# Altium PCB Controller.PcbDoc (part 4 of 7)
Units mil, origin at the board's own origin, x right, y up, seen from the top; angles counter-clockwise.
Board outline 9000 x 8000 mil, 6 copper layers (Top Layer, Layer 1, Layer 2, Layer 3, Layer 4, Bottom Layer), stack 61.699 mil thick; 761 components, 454 nets, 2369 pads, 1133 vias.
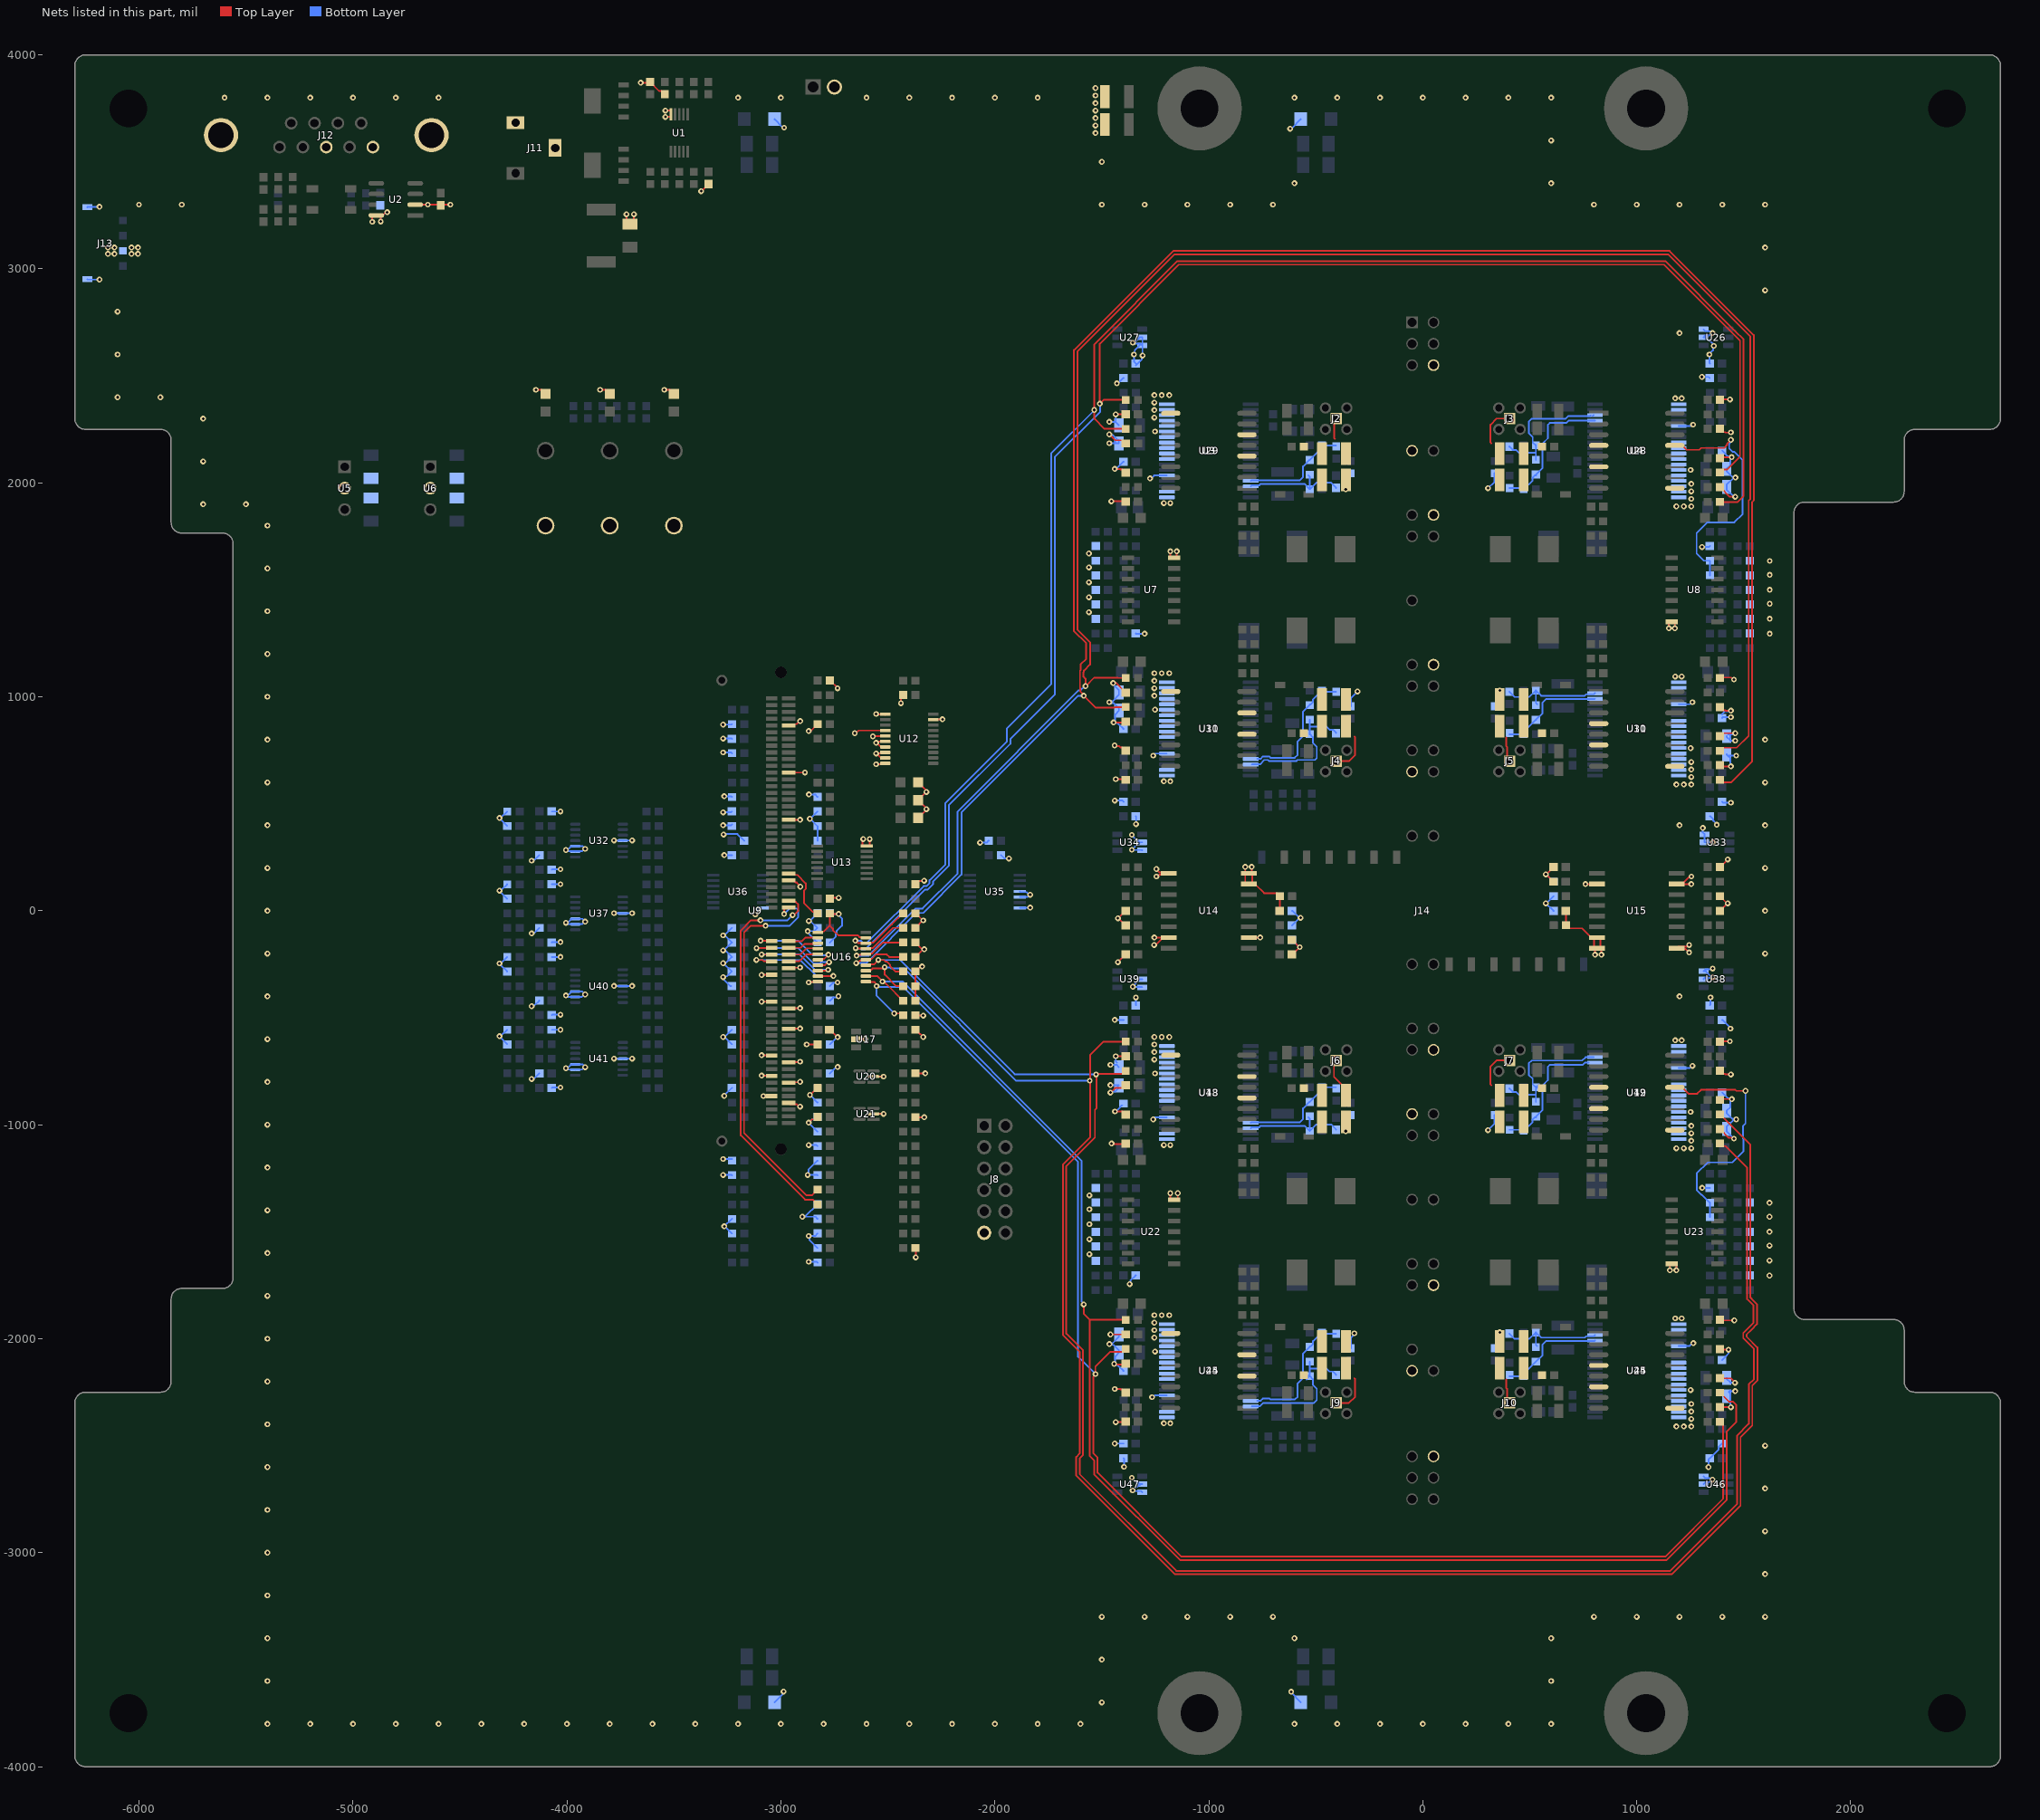
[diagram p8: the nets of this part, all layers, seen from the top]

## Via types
v1: diameter 27, hole 13, Top Layer to Bottom Layer, tented both sides, 1133 vias

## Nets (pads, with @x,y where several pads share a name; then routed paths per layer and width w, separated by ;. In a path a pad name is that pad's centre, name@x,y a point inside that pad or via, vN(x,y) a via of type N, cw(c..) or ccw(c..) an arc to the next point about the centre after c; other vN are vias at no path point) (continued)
F\L\T\_\4\P\: R193.1 R195.2 U4.13 | length 1165.1
  Top Layer w8: U4.13@1177.78,2175 1211.65,2175 1232.15,2154.5 1291.65,2154.5 1300.01,2162.86 1407.86,2162.86 1422.12,2177.12 1422.12,2182.77 1439.89,2200.55 v1(1439.89,2201.06)
  Bottom Layer w8: R195.2@1341.38,1568 R193.1@1341.38,1636 1314,1636 1279.7,1670.3 1279.7,1764.7 1330,1815 1456.06,1815 1495,1853.94 1495,2105 1454.69,2145.31 1446.94,2145.31 1432,2160.25 1432,2181.38 1436.25,2185.63 1436.25,2197.43 v1(1439.89,2201.06)
F\L\T\_\4\S\: R336.1 R339.2 U19.13 | length 1134
  Top Layer w8: U19.13@1177.78,-825 1211.65,-825 1241.65,-855 1282.15,-855 1300.01,-837.14 1460.33,-837.14 1464.94,-841.75 v1(1508.25,-841.75)
  Bottom Layer w8: R339.2@1341.38,-1432 R336.1@1341.38,-1364 1340.47,-1364 1304.28,-1327.8 1302.24,-1327.8 1280,-1305.56 1280,-1227.63 1331.63,-1176 1446.63,-1176 1499,-1123.63 1499,-1066.89 1496,-1063.89 1496,-1007.14 1508.25,-994.89 v1(1508.25,-841.75)
FBVDD_1P: C130.1 R212.1 R215.2 U30.34 | length 503.5
  Bottom Layer w8: C130.1@405,1023.58 405,1022.63 428.58,999.04 497.76,999.04 527.72,1029 R212.1@528.62,1029 ; R215.2@535,965 528.62,971.38 R212.1@528.62,1029 ; U30.34@804.13,1016.34 799.4,1011.61 763.89,1011.61 757.28,1005 553.53,1005 529.53,1029 R212.1@528.62,1029
FBVDD_1S: C249.1 R362.1 R365.2 U44.34 | length 503.5
  Bottom Layer w8: C249.1@405,-1976.42 405,-1977.37 428.58,-2000.96 497.76,-2000.96 527.72,-1971 R362.1@528.62,-1971 ; R365.2@535,-2035 528.62,-2028.62 R362.1@528.62,-1971 ; U44.34@804.13,-1983.66 799.4,-1988.39 763.89,-1988.39 757.28,-1995 553.53,-1995 529.53,-1971 R362.1@528.62,-1971
FBVDD_2P: C139.1 R219.2 R224.1 U31.34 | length 647.2
  Bottom Layer w8: U31.34@-798.66,683.66 -797.73,684.6 -760.4,684.6 -740,705 -724.28,705 -718.28,699 -591.72,699 -585.72,705 -503.88,705 -495.36,713.52 -495.36,766.98 -513.76,785.39 -513.76,811.04 -527.72,825 R224.1@-528.62,825 -528.62,860 R219.2@-528.62,893 ; -525,860 -450,860 -436.24,846.24 -419.86,846.24 -405,831.37 C139.1@-405,830.42
FBVDD_2S: C257.1 R368.2 R371.1 U45.34 | length 662.6
  Bottom Layer w8: U45.34@-798.66,-2316.34 -797.73,-2315.4 -760.4,-2315.4 -745,-2300 -508.88,-2300 -495.36,-2286.48 -495.36,-2233.02 -513.76,-2214.61 -513.76,-2188.96 -527.72,-2175 R371.1@-528.62,-2175 R371.1@-529.53,-2175 ; R371.1@-543.48,-2189.86 -543.48,-2188.96 R371.1@-532.26,-2177.74 ; R371.1@-535,-2175 -528.62,-2168.62 R368.2@-528.62,-2107 ; -525,-2140 -450,-2140 -436.24,-2153.76 -419.86,-2153.76 -405,-2168.63 C257.1@-405,-2169.58
FBVDD_3P: C111.1 R181.2 R184.1 U29.34 | length 503.5
  Bottom Layer w8: U29.34@-804.13,1983.66 -799.4,1988.39 -763.89,1988.39 -757.28,1995 -553.53,1995 -529.53,1971 R184.1@-528.62,1971 ; R181.2@-535,2035 -528.62,2028.62 R184.1@-528.62,1971 ; C111.1@-405,1976.42 -405,1977.37 -428.58,2000.96 -497.76,2000.96 -527.72,1971 R184.1@-528.62,1971
FBVDD_3S: C226.1 R318.2 R322.1 U43.34 | length 503.5
  Bottom Layer w8: U43.34@-804.13,-1016.34 -799.4,-1011.61 -763.89,-1011.61 -757.28,-1005 -553.53,-1005 -529.53,-1029 R322.1@-528.62,-1029 ; R318.2@-535,-965 -528.62,-971.38 R322.1@-528.62,-1029 ; C226.1@-405,-1023.58 -405,-1022.63 -428.58,-999.04 -497.76,-999.04 -527.72,-1029 R322.1@-528.62,-1029
FBVDD_4P: C100.1 R174.1 R177.2 U28.34 | length 634.7
  Bottom Layer w8: C100.1@405,2169.58 405,2168.63 419.86,2153.76 436.24,2153.76 450,2140 525,2140 ; R177.2@528.62,2107 R174.1@528.62,2175 527.72,2175 513.76,2188.96 513.76,2214.61 495.36,2233.02 495.36,2286.48 508.88,2300 667.37,2300 678.98,2311.61 781.61,2311.61 U28.34@785,2315 ; U28.34@793.93,2311.61 U28.34@798.66,2316.34
FBVDD_4S: C216.1 R306.1 R312.2 U42.34 | length 662.6
  Bottom Layer w8: C216.1@405,-830.42 405,-831.37 419.86,-846.24 436.24,-846.24 450,-860 525,-860 ; R312.2@528.62,-893 528.62,-831.38 R306.1@535,-825 ; R306.1@529.53,-825 R306.1@528.62,-825 527.72,-825 513.76,-811.04 513.76,-785.39 495.36,-766.98 495.36,-713.52 508.88,-700 745,-700 760.4,-684.6 797.73,-684.6 U42.34@798.66,-683.66 ; R306.1@532.26,-822.26 543.48,-811.04 R306.1@543.48,-810.14
FBVEE_1P: C138.1 R220.2 R223.1 U30.33 | length 504.5
  Bottom Layer w8: R220.2@405,825 R223.1@471.38,825 472.28,825 486.24,838.96 486.24,851.61 527.63,893 C138.1@528.58,893 529.53,893 560,923.47 560,973.47 575.53,989 802.39,989 U30.33@804.13,990.75
FBVEE_1S: C256.1 R369.2 R370.1 U44.33 | length 504.5
  Bottom Layer w8: R369.2@405,-2175 R370.1@471.38,-2175 472.28,-2175 486.24,-2161.04 486.24,-2148.39 527.63,-2107 C256.1@528.58,-2107 529.53,-2107 560,-2076.53 560,-2026.53 575.53,-2011 802.39,-2011 U44.33@804.13,-2009.25
FBVEE_2P: C133.1 R213.1 R214.2 U31.33 | length 619.1
  Bottom Layer w8: U31.33@-775,710 -757.63,710 -746.63,721 -717.66,721 -711.66,715 -598.34,715 -584.64,728.7 -584.64,791.36 -559.48,816.52 -559.48,931.04 C133.1@-529.05,961.48 ; C133.1@-529.05,965 -523.63,965 -512.76,975.86 -512.76,988.52 -472.28,1029 -466.91,1023.62 R214.2@-405,1023.62
FBVEE_2S: C252.1 R363.1 R364.2 U45.33 | length 617
  Bottom Layer w8: U45.33@-775,-2290 -757.63,-2290 -747.63,-2280 -716.66,-2280 -713.12,-2283.54 -596.88,-2283.54 -584.64,-2271.3 -584.64,-2208.39 -559.48,-2183.23 -559.48,-2068.96 C252.1@-529.05,-2038.52 ; C252.1@-529.05,-2035 -523.63,-2035 -512.76,-2024.14 -512.76,-2011.48 -472.28,-1971 -466.91,-1976.38 R364.2@-405,-1976.38
FBVEE_3P: C105.1 R175.1 R176.2 U29.33 | length 504.5
  Bottom Layer w8: U29.33@-804.13,2009.25 -802.39,2011 -575.53,2011 -560,2026.53 -560,2076.53 -529.53,2107 C105.1@-528.58,2107 -527.63,2107 -486.24,2148.39 -486.24,2161.04 -472.28,2175 R175.1@-471.38,2175 R176.2@-405,2175
FBVEE_3S: C219.1 R307.1 R311.2 U43.33 | length 504.5
  Bottom Layer w8: U43.33@-804.13,-990.75 -802.39,-989 -575.53,-989 -560,-973.47 -560,-923.47 -529.53,-893 C219.1@-528.58,-893 -527.63,-893 -486.24,-851.61 -486.24,-838.96 -472.28,-825 R307.1@-471.38,-825 R311.2@-405,-825
FBVEE_4P: C109.1 R182.2 R183.1 U28.33 | length 643.6
  Bottom Layer w8: R182.2@405,1976.38 466.91,1976.38 472.28,1971 512.76,2011.48 512.76,2024.14 523.63,2035 C109.1@529.05,2035 ; C109.1@529.05,2038.52 559.48,2068.96 559.48,2183.23 584.64,2208.39 584.64,2271.3 593.34,2280 670,2280 680.75,2290.75 U28.33@804.13,2290.75
FBVEE_4S: C223.1 R320.2 R321.1 U42.33 | length 614.1
  Bottom Layer w8: R320.2@405,-1023.62 466.91,-1023.62 472.28,-1029 512.76,-988.52 512.76,-975.86 523.63,-965 C223.1@529.05,-965 ; C223.1@529.05,-961.48 559.48,-931.04 559.48,-816.77 584.64,-791.61 584.64,-728.7 593.34,-720 747.63,-720 757.63,-710 U42.33@775,-710
G1P_PWM: U9.49 U16.5 | length 150.1
  Top Layer w8: U9.49@-2963.58,-236.22 -2913.54,-236.22 -2880.52,-203.2 U16.5@-2827.2,-203.2
G1P_PWM_BUF: R46.1 R57.1 R83.2 U16.15 | length 9592.6
  Top Layer w8: v1(-2647.6,-244.65) -2642.54,-244.65 -2630.55,-232.67 -2606.67,-232.67 -2598.92,-224.92 -2575.98,-224.92 -2555.56,-204.5 -2505.27,-204.5 -2493.77,-216 R83.2@-2428.62,-216 ; R46.1@-1388.62,952 -1438.27,952 -1440.77,949.5 -1529.5,949.5 v1(-1585,1005) -1585,1009.06 -1601,1025.06 -1601,1038.44 -1602,1039.44 -1602,1121.63 -1599.47,1124.16 -1599.47,1150.53 -1573.5,1176.5 -1573.5,1250.34 -1630,1306.84 -1630,2620.51 -1166.51,3084 1153.12,3084 1547,2690.12 1547,1918.06 1539,1910.06 1539,697.94 1440.56,599.5 1401.12,599.5 R57.1@1388.62,612
  Bottom Layer w8: v1(-2647.6,-244.65) -2647.51,-244.56 -2601.74,-244.56 -2367.18,-10 -2335,-10 -2156,169 -2156,459 -1610.5,1004.5 -1585.5,1004.5 v1(-1585,1005)
G1S_PWM: U9.50 U16.9 | length 537.8
  Top Layer w8: v1(-3114.5,-230) -3085.75,-230 -3080.9,-234.85 -3043.69,-234.85 U9.50@-3042.32,-236.22 ; U16.9@-2827.2,-305.57 -2826.64,-305 v1(-2755,-305)
  Bottom Layer w8: v1(-3114.5,-230) -2908.94,-230 -2833.94,-305 v1(-2755,-305)
G1S_PWM_BUF: R92.2 R148.1 R155.1 U16.11 | length 6836.6
  Top Layer w8: U16.11@-2596.35,-332.34 -2595.61,-333.08 -2562.25,-333.08 -2548.06,-347.27 v1@-2548.06,-348 ; v1(-2552.83,-351.72) -2551.78,-351.72 v1@-2548.06,-348 ; v1@-2548.06,-359.13 v1@-2548.06,-348 ; v1(-2470,-480) -2436.62,-480 R92.2@-2428.62,-488 R92.2@-2429.53,-488 ; R148.1@-1388.62,-2048 -1402.58,-2061.96 -1461.96,-2061.96 -1530,-2130 -1530,-2169.19 -1540,-2179.19 -1540,-2535 -1520,-2555 -1520,-2626.35 -1127.72,-3018.63 1132.72,-3018.63 1403.48,-2747.87 1403.48,-2401.96 1389.53,-2388 R155.1@1388.62,-2388
  Bottom Layer w8: v1(-2470,-480) -2552.83,-397.17 v1(-2552.83,-351.72) -2549.2,-355.36 -2536.2,-355.36 -2535.56,-356 -2429,-356 -1611,-1174 -1611,-2084 v1(-1530,-2165)
G2P_PWM: U9.51 U16.4 | length 150.3
  Top Layer w8: U9.51@-2963.58,-204.72 -2910.58,-204.72 -2880.86,-175 U16.4@-2825.57,-175
G2P_PWM_BUF: R40.1 R53.1 R81.2 U16.16 | length 9337.7
  Top Layer w8: v1(-2646.15,-209.68) -2642.91,-206.44 -2607.26,-206.44 U16.16@-2603.41,-202.59 ; U16.16@-2602.8,-203.2 -2598.92,-199.33 -2573.02,-199.33 -2521.69,-148 R81.2@-2428.62,-148 ; R40.1@-1389.53,1088 -1425.62,1088 -1427.21,1089.59 -1449.35,1089.59 -1449.44,1089.5 -1535.5,1089.5 -1575,1050 v1(-1576.5,1050) -1576.5,1084.38 -1586,1093.88 -1586,1115 -1583.47,1117.53 -1583.47,1122.59 -1555,1151.06 -1555,1254.47 -1614,1313.47 -1614,2613.88 -1159.88,3068 1146.49,3068 1531,2683.49 1531,1924.68 1523,1916.68 1523,818 1466.96,761.96 1402.58,761.96 R53.1@1388.62,748
  Bottom Layer w8: v1(-2646.15,-209.68) -2646.06,-209.59 -2589.4,-209.59 -2369.81,10 -2337.63,10 -2175,172.63 -2175,462.63 -1607.63,1030 -1599.69,1030 -1579.69,1050 v1(-1576.5,1050)
G2S_PWM: U9.52 U16.8 | length 438.1
  Top Layer w8: v1(-3090,-204.5) -3089.89,-204.61 -3042.44,-204.61 U9.52@-3042.32,-204.72 ; U16.8@-2827.2,-279.98 -2790.12,-279.98 -2789.69,-279.55 -2782.72,-279.55 v1(-2779.09,-275.91)
  Bottom Layer w8: v1(-3090,-204.5) -2911.81,-204.5 -2840.4,-275.91 v1(-2779.09,-275.91)
G2S_PWM_BUF: R90.2 R144.1 R153.1 U16.12 | length 6959.8
  Top Layer w8: U16.12@-2602.8,-305.57 -2602.51,-305.28 -2549.72,-305.28 v1@-2525,-330 ; v1(-2525,-330.5) v1@-2525,-330 ; R90.2@-2428.62,-420 -2429.53,-420 -2504.58,-344.95 -2504.91,-344.95 -2512.15,-337.71 -2512.65,-337.71 -2519.86,-330.5 -2519.86,-330 v1@-2525,-330 ; v1(-1585,-1840) -1585,-1883 -1556,-1912 ; R144.1@-1388.62,-1912 -1556,-1912 ; R153.1@1388.62,-2252 1389.53,-2252 1432.03,-2294.5 1450.56,-2294.5 1465.5,-2309.44 1465.5,-2388.48 1420,-2433.98 1420,-2753.98 1139.35,-3034.63 -1134.35,-3034.63 -1536,-2632.98 -1536,-2569 -1556,-2549 -1556,-1912
  Bottom Layer w8: v1(-2525,-330.5) -2524.5,-330 -2432.37,-330 -1595,-1167.37 -1595,-1825.81 -1585,-1835.81 v1(-1585,-1840)
G3P_PWM: U9.53 U16.3 | length 147.4
  Top Layer w8: U9.53@-2963.58,-173.23 -2907.63,-173.23 -2889.4,-155 U16.3@-2823.73,-155
G3P_PWM_BUF: R16.1 R23.1 R79.2 U16.17 | length 7692.7
  Top Layer w8: v1(-2650.66,-174.97) -2649.34,-176.29 -2606.5,-176.29 -2603.99,-178.81 -2598.92,-173.74 -2570.06,-173.74 -2476.32,-80 R79.2@-2428.62,-80 ; v1(-1509.5,2370) -1509.5,2650.5 -1140,3020 1126.61,3020 1483,2663.61 1483,2123.34 1421.61,2061.96 1402.58,2061.96 R23.1@1388.62,2048 ; v1@-1509.5,2370.44 -1491.94,2388 R16.1@-1388.62,2388
  Bottom Layer w8: v1(-2650.66,-174.97) -2648.1,-177.54 -2625.16,-177.54 -2622.7,-180 -2605,-180 -2325.95,99.05 -2320.7,99.05 -2320.46,99.29 -2313.15,99.29 -2289,123.44 -2289,136 -2215,210 -2215,492.63 -1927.5,780.13 -1927.5,802.5 -1720,1010 -1720,2120 -1507.53,2332.47 -1507.53,2368.03 v1(-1509.5,2370)
G3S_PWM: U9.54 U16.7 | length 500.5
  Top Layer w8: v1(-3113.92,-174.9) -3113.09,-174.06 -3043.16,-174.06 U9.54@-3042.32,-173.23 ; U16.7@-2827.2,-254.39 -2794.39,-254.39 -2780,-240 v1(-2775,-240)
  Bottom Layer w8: v1(-3113.92,-174.9) -2918.78,-174.9 -2848.68,-245 -2816.91,-245 -2811.91,-240 v1(-2775,-240)
G3S_PWM_BUF: R88.2 R94.1 R109.1 U16.13 | length 9082.6
  Top Layer w8: U16.13@-2620.47,-275 -2576.1,-275 -2570.34,-269.25 -2545.75,-269.25 -2545,-270 v1@-2515,-270 ; v1(-2515,-263.5) v1@-2515,-270 ; R88.2@-2428.62,-352 -2461.49,-352 -2515,-298.49 v1@-2515,-270 ; v1(-1556.5,-794.17) -1555,-795.67 -1555,-1059.75 -1682,-1186.75 -1682,-1982.75 -1604,-2060.75 -1604,-2536.63 -1620,-2552.63 -1620,-2639.49 -1158.49,-3101 1163.49,-3101 1484.75,-2779.75 1484.75,-2459.75 1540,-2404.49 1540,-2219.83 1564,-2195.83 1564,-2041.12 1513.5,-1990.62 1513.5,-1980.44 1536.04,-1957.91 1562,-1931.94 1562,-1838.57 1536.04,-1812.61 1531,-1807.57 1531,-1093.47 1389.53,-952 R109.1@1388.62,-952 ; v1@-1555,-794.17 -1555,-674 -1493,-612 R94.1@-1388.62,-612
  Bottom Layer w8: v1(-2515,-263.5) -2513.25,-265.25 -2489.5,-265.25 -2485.5,-269.25 -2425.24,-269.25 -1900.32,-794.17 v1(-1556.5,-794.17)
G4P_PWM: U9.55 U16.2 | length 148.6
  Top Layer w8: U9.55@-2963.58,-141.73 -2901.73,-141.73 -2885,-125 U16.2@-2821.92,-125
G4P_PWM_BUF: R18.1 R27.1 R75.2 U16.18 | length 7997.1
  Top Layer w8: v1(-2652.01,-140) -2649.86,-140 -2638.42,-151.44 -2603.38,-151.44 U16.18@-2602.8,-152.02 -2599,-148.23 -2567.17,-148.23 -2482.94,-64 -2481.53,-64 -2429.53,-12 R75.2@-2428.62,-12 ; v1(-1535.53,2340.53) -1535,2341.06 -1535,2647.63 -1146.63,3036 1133.24,3036 1460,2709.24 1499,2670.24 1499,1937.94 1470.56,1909.5 1391.12,1909.5 R27.1@1388.62,1912 ; v1@-1535,2340.53 -1535,2300 -1487,2252 R18.1@-1388.62,2252
  Bottom Layer w8: v1(-2652.01,-140) -2626.8,-140 -2618.74,-148.06 -2595.69,-148.06 -2332.58,115.05 -2327.33,115.05 -2327.09,115.29 -2319.77,115.29 -2305,130.07 -2305,142.63 -2231,216.63 -2231,504 -1943.5,791.5 -1943.5,852.5 -1736,1060 -1736,2139 -1535.53,2339.47 v1(-1535.53,2340.53)
G4S_PWM: U9.56 U16.6 | length 458.5
  Top Layer w8: v1(-3095,-140) -3094.13,-140.87 -3043.19,-140.87 U9.56@-3042.32,-141.73 ; U16.6@-2827.2,-228.8 -2823.33,-224.92 -2798.08,-224.92 v1(-2778.32,-205.16)
  Bottom Layer w8: v1(-3095,-140) -2920,-140 -2851.46,-208.54 -2781.7,-208.54 v1(-2778.32,-205.16)
G4S_PWM_BUF: R87.2 R99.1 R116.1 U16.14 | length 8781.3
  Top Layer w8: U16.14@-2602.8,-254.39 -2598.92,-250.51 -2565.51,-250.51 v1(-2545,-230) -2518.94,-230 -2510.94,-238 -2504.44,-238 -2489.5,-252.94 -2489.5,-259.44 -2464.94,-284 R87.2@-2428.62,-284 ; v1(-1527,-765) -1525,-767 -1525,-923.69 -1532.5,-931.19 -1532.5,-1059.87 -1666,-1193.37 -1666,-1976.12 -1588,-2054.12 -1588,-2543.25 -1604,-2559.25 -1604,-2632.86 -1151.86,-3085 1156.86,-3085 1468.43,-2773.43 1468.43,-2453.43 1524,-2397.86 1524,-2213.21 1548,-2189.21 1548,-2047.75 1497.5,-1997.25 1497.5,-1973.82 1520.04,-1951.28 1546,-1925.32 1546,-1845.2 1520.04,-1819.24 1515,-1814.2 1515,-1200 1414.7,-1099.7 1400.33,-1099.7 R116.1@1388.62,-1088 ; v1@-1525,-765 -1521.96,-761.96 -1402.58,-761.96 R99.1@-1388.62,-748
  Bottom Layer w8: v1(-2545,-230) -2441.86,-230 -1907.86,-764 -1563.39,-764 -1562.39,-765 v1(-1527,-765)
G_1P: J5.1 J14.034 R44.2 R49.2 R51.2 R216.2 | length 195.7
  Top Layer w8: 390,810 390,770 395,765 395,709.61 J5.1@405,699.61
  Bottom Layer w8: R216.2@350,955 350.96,955.96 350.96,1015.81 360,1024.86 v1(360,1030)
G_1S: J10.1 J14.092 R147.2 R150.2 R152.2 R366.2 | length 195.7
  Top Layer w8: 390,-2190 390,-2230 395,-2235 395,-2290.39 J10.1@405,-2300.39
  Bottom Layer w8: R366.2@350,-2045 350.96,-2044.04 350.96,-1984.19 360,-1975.14 v1(360,-1970)
G_2P: J4.1 J14.043 R43.2 R48.2 R50.2 R217.2 | length 270.7
  Top Layer w8: J4.1@-405,699.61 -345.39,699.61 -316.62,728.38 -316.62,811.62 -320,815
  Bottom Layer w8: R217.2@-335,955 -335,995 v1(-305,1025)
G_2S: J9.1 J14.099 R146.2 R149.2 R151.2 R367.2 | length 264.5
  Top Layer w8: J9.1@-405,-2300.39 -345.39,-2300.39 -316.62,-2271.62 -316.62,-2188.38 -320,-2185
  Bottom Layer w8: R367.2@-335,-2045 -335,-1995.14 -320,-1980.14 v1(-320,-1975)
G_3P: J2.1 J14.020 R19.2 R21.2 R24.2 R179.2 | length 176.1
  Top Layer w8: J2.1@-414.61,2300 -414.61,2209.61 -410,2205
  Bottom Layer w8: v1(-360,1970) -360,1975.14 -350.96,1984.19 -350.96,2044.04 R179.2@-350,2045
G_3S: J6.1 J14.075 R103.2 R105.2 R110.2 R316.2 | length 269.9
  Top Layer w8: J6.1@-405,-699.61 -415,-709.61 -415,-776.39 -358.9,-832.49 R105.2@-358.9,-863
  Bottom Layer w8: v1(-360,-1030) -360,-1024.86 -350.96,-1015.81 -350.96,-955.96 R316.2@-350,-955
G_4P: J3.1 J14.013 R20.2 R22.2 R25.2 R178.2 | length 270.7
  Top Layer w8: 320,2185 316.62,2188.38 316.62,2271.62 345.39,2300.39 J3.1@405,2300.39
  Bottom Layer w8: v1(305,1975) 335,2005 R178.2@335,2045
G_4S: J7.1 J14.070 R104.2 R106.2 R111.2 R315.2 | length 270.7
  Top Layer w8: 320,-815 316.62,-811.62 316.62,-728.38 345.39,-699.61 J7.1@405,-699.61
  Bottom Layer w8: v1(305,-1025) 335,-995 R315.2@335,-955
GD_DIS: R74.1 U9.67 | length 277.1
  Top Layer w8: U9.67@-2963.58,173.23 -2957.74,167.39 -2923.45,167.39 -2884.1,128.04 -2884.1,102.11 -2892.34,93.87 -2892.34,36.25 -2850,-6.09 -2834.57,-6.09 R74.1@-2828.67,-12
GD_DIS_FILT: C176.1 R74.2 R269.2 U16.1 U16.19 | length 575.7
  Top Layer w8: U16.1@-2827.2,-100.84 -2823.33,-96.97 -2799.81,-96.97 -2771.42,-68.58 ; v1(-2730,-15) -2768.42,-15 R74.2@-2771.42,-12 -2771.42,-15 -2771.42,-68.58 ; U16.19@-2596.19,-122.56 -2633.39,-122.56 -2641.45,-114.5 -2731.56,-114.5 -2756.5,-89.56 -2756.5,-83.5 -2771.42,-68.58
  Bottom Layer w8: R269.2@-2771.38,-148 -2770.47,-148 -2744.5,-122.03 -2744.5,-108.72 -2739.61,-103.83 -2739.61,-95.53 -2714.5,-70.42 -2714.5,-35.56 -2730,-20.06 v1(-2730,-15) -2768.42,-15 C176.1@-2771.42,-12
GH_1P: R44.1 U11.4
GH_1S: R147.1 U25.4
GH_2P: R48.1 U10.4
GH_2S: R149.1 U24.4
GH_3P: R24.1 U3.4
GH_3S: R110.1 U18.4
GH_4P: R22.1 U4.4
GH_4S: R106.1 U19.4
GL_1P: R49.1 U11.6
GL_1S: R150.1 U25.6
GL_2P: R43.1 U10.6
GL_2S: R146.1 U24.6
GL_3P: R21.1 U3.6
GL_3S: R105.1 U18.6
GL_4P: R25.1 U4.6
GL_4S: R111.1 U19.6
GND: C1.2 C2.2 C4.2 C6.2 C7.2 C10.2 C13.2 C14.2 C15.2 C16.2 C17.2 C18.2 C23.2 C24.2 C25.2 C26.2 C27.2 C28.2 C29.2 C30.2 C31.2 C34.2 C37.2 C39.2 C42.2 C43.2 C44.2 C45.2 C48.2 C49.2 C52.2 C54.2 C55.2 C56.2 C59.2 C62.2 C63.2 C64.2 C65.2 C66.2 C67.2 C68.2 C69.2 C72.2 C75.2 C76.2 C77.2 C78.2 C79.2 C80.2 C83.2 C86.2 C87.2 C89.2 C90.2 C91.2 C92.2 C97.2 C99.2 C101.2 C102.2 C103.2 C106.2 C108.2 C112.2 C113.2 C114.2 C115.2 C116.2 C117.2 C118.2 C119.2 C120.2 C121.2 C122.2 C123.2 C124.2 C125.2 C126.2 C127.2 C128.2 C129.2 C135.2 C137.2 C140.2 C141.2 C142.2 C146.2 C151.2 C152.2 C153.2 C154.2 C155.2 C156.2 C157.2 C158.2 C159.2 C160.2 C161.2 C162.2 C163.2 C164.2 C165.2 C166.2 C168.2 C169.2 C171.2 C173.2 C176.2 C178.2 C179.2 C181.2 C183.2 C184.2 C185.2 C186.2 C187.2 C188.2 C189.2 C190.2 C191.2 C193.2 C194.2 C195.2 C196.2 C197.2 C198.2 C199.2 C200.2 C201.2 C202.2 C203.2 C208.2 C209.2 C211.2 C213.2 C214.2 C215.2 C217.2 C220.2 C222.2 C224.2 C227.2 C228.2 C229.2 C230.2 C231.2 C232.2 C233.2 C234.2 C235.2 C236.2 C237.2 C238.2 C239.2 C240.2 C241.2 C242.2 C243.2 C244.2 C245.2 C246.2 C247.2 C248.2 C254.2 C255.2 C258.2 C259.2 C263.2 C267.2 C268.2 C269.2 C270.2 D1.1 D2.1 D3.1 D16.1 D17.1 D18.1 D31.1 D32.1 D41.1 D42.1 J1.2 J8.11 J11.2 J11.3 J12.3 J12.5 J12.10 J12.11 J13.2 J13.MH1 J13.MH2 J14.006 J14.108 R1.1 R5.1 R6.1 R75.1 R79.1 R81.1 R83.1 R87.1 R88.1 R90.1 R92.1 R93.2 R101.1 R112.1 R222.1 R227.1 R241.1 R243.1 R259.1 R269.1 R273.1 R290.1 R313.1 R326.1 R330.1 R331.1 R341.1 R344.1 R347.1 R351.1 TP4.1 TP5.1 TP6.1 U1.5 U2.2 U2.8 U3.9 U4.9 U5.2 U6.2 U7.7 U8.7 U9.7 U9.10 U9.13 U9.16 U9.19 U9.22 U9.29 U9.35 U9.38 U9.46 U9.47 U9.65 U9.83 U9.97 U9.111 U10.9 U11.9 U12.1 U12.4 U12.5 U12.6 U12.7 U12.8 U12.9 U12.10 U12.19 U13.7 U14.9 U14.15 U15.9 U15.15 U16.10 U17.2 U18.9 U19.9 U20.2 U21.2 U22.7 U23.7 U24.9 U25.9 U26.2 U26.3 U27.2 U27.3 U28.1 U28.2 U28.5 U28.8 U28.9 U28.10 U28.11 U28.12 U28.13 U28.14 U28.15 U28.16 U28.17 U28.18 U29.1 U29.2 U29.5 U29.8 U29.9 U29.10 U29.11 U29.12 U29.13 U29.14 U29.15 U29.16 U29.17 U29.18 U30.1 U30.2 U30.5 U30.8 U30.9 U30.10 U30.11 U30.12 U30.13 U30.14 U30.15 U30.16 U30.17 U30.18 U31.1 U31.2 U31.5 U31.8 U31.9 U31.10 U31.11 U31.12 U31.13 U31.14 U31.15 U31.16 U31.17 U31.18 U32.2 U32.3 U32.11 U33.2 U33.3 U34.2 U34.3 U35.4 U35.5 U35.7 U36.7 U37.2 U37.3 U37.11 U38.2 U38.3 U39.2 U39.3 U40.2 U40.3 U40.11 U41.2 U41.3 U41.11 U42.1 U42.2 U42.5 U42.8 U42.9 U42.10 U42.11 U42.12 U42.13 U42.14 U42.15 U42.16 U42.17 U42.18 U43.1 U43.2 U43.5 U43.8 U43.9 U43.10 U43.11 U43.12 U43.13 U43.14 U43.15 U43.16 U43.17 U43.18 U44.1 U44.2 U44.5 U44.8 U44.9 U44.10 U44.11 U44.12 U44.13 U44.14 U44.15 U44.16 U44.17 U44.18 U45.1 U45.2 U45.5 U45.8 U45.9 U45.10 U45.11 U45.12 U45.13 U45.14 U45.15 U45.16 U45.17 U45.18 U46.2 U46.3 U47.2 U47.3 | length 17168.2
  Top Layer w8: v1(-4910,3220) -4910,3243.84 -4903.84,3250 U2.8@-4891.09,3250 -4861.35,3250 -4849.99,3261.36 -4843.64,3261.36 v1(-4840,3265) ; v1(-4870,3221.16) U2.8@-4870,3245 ; U2.2@-4708.91,3300 v1(-4650,3300) -4593.58,3300 C4.2@-4590,3296.42 -4586.42,3300 v1(-4545,3300) ; v1(-4145,2435) -4118.66,2435 D1.1@-4100,2416.34 ; v1(-3845,2435) -3818.66,2435 D2.1@-3800,2416.34 ; v1(-3721.73,3255) -3721.73,3225.92 C6.2@-3705,3209.19 -3686.73,3227.45 v1(-3686.73,3255) ; v1(-3655,3870) -3613.63,3870 C1.2@-3611,3872.63 ; C1.2@-3611,3873.58 C1.2@-3611,3872.63 ; v1(-3545,2435) -3518.66,2435 D3.1@-3500,2416.34 ; R1.1@-3543,3816.38 -3543,3817.28 -3556.96,3831.24 -3569.61,3831.24 C1.2@-3611,3872.63 ; v1(-3540,3710) -3516.28,3710 -3514.37,3711.91 U1.5@-3514.37,3722.09 -3514.37,3738.09 -3516.28,3740 v1(-3540,3740) ; v1(-3372.99,3363.21) -3371.26,3363.21 -3333.05,3401.42 C2.2@-3330,3401.42 ; v1(-3090,-770) -3089.17,-770.83 -3043.15,-770.83 U9.16@-3042.32,-771.65 ; v1(-3090,-675) -3088.92,-676.08 -3043.41,-676.08 U9.22@-3042.32,-677.17 ; v1(-3090,-425) -3089.9,-425.1 -3042.42,-425.1 U9.38@-3042.32,-425.2 ; v1(-3090,-300) -3089.61,-299.61 -3042.72,-299.61 U9.46@-3042.32,-299.21 ; v1(-3081.92,-866.07) -3042.39,-866.07 U9.10@-3042.32,-866.14 ; U9.7@-2963.58,-897.64 -2957.74,-903.48 -2926.66,-903.48 -2915.14,-915 v1(-2910,-915) ; U9.13@-2963.58,-803.15 -2961.74,-801.31 -2912.37,-801.31 v1(-2910.53,-799.47) ; U9.19@-2963.58,-708.66 -2961.75,-706.83 -2911.83,-706.83 v1(-2910,-705) ; U9.29@-2963.58,-551.18 -2962.99,-550.59 -2910.59,-550.59 v1(-2910,-550) ; U9.35@-2963.58,-456.69 -2962.74,-455.85 -2910.85,-455.85 v1(-2910,-455) ; U9.47@-2963.58,-267.72 -2962.22,-266.36 -2911.36,-266.36 v1(-2910,-265) ; U9.65@-2963.58,141.73 -2940.94,141.73 -2931.29,132.08 -2926.13,132.08 -2909.6,115.55 v1(-2909.6,112.67) ; U9.83@-2963.58,425.2 -2963.48,425.1 -2910.1,425.1 v1(-2910,425) ; U9.97@-2963.58,645.67 -2963.29,645.96 -2887.63,645.96 v1(-2887.33,646.26) ; U9.111@-2963.58,866.14 -2957.74,871.98 -2927.19,871.98 -2912.76,886.42 v1(-2909.65,886.42) ; v1(-2880,-625) -2829.58,-625 C56.2@-2828.58,-624 ; v1(-2870,-990) -2854.94,-974.94 -2839.52,-974.94 C67.2@-2828.58,-964 ; v1(-2870,-335) -2868.08,-333.08 -2829.13,-333.08 U16.10@-2827.2,-331.16 ; v1(-2870,840) -2866.36,843.64 -2857.89,843.64 -2829.53,872 C29.2@-2828.58,872 ; v1(-2864.08,-860.83) -2862.36,-860.83 -2829.53,-828 C64.2@-2828.58,-828 ; R93.2@-2773.38,-556 -2770.47,-556 -2736.16,-590.31 v1(-2734.69,-590.31) ; C44.2@-2771.42,56 -2767.42,60 v1(-2730,60) ; C24.2@-2771.42,1076 -2770.47,1076 -2735,1040.53 v1(-2735,1040) ; v1@-2736.92,-333.08 v1(-2735,-335) ; v1(-2655,830) -2649.86,830 -2637.47,842.39 U12.4@-2512.2,842.39 ; U17.2@-2648.23,-601 -2647.23,-600 v1(-2605,-600) ; v1(-2615,335) -2618.64,331.36 -2618.64,305.77 -2615.64,302.77 U13.7@-2598.75,302.77 -2588,302.77 -2585,305.77 v1(-2585,335) ; U20.2@-2572.56,-774.75 -2572.35,-774.95 -2520.05,-774.95 v1(-2520,-774.91) ; v1@-2569.1,815.9 -2513.1,815.9 U12.5@-2512.2,816.8 ; U21.2@-2566.14,-947.43 -2563.57,-950 -2556.71,-950 -2555.82,-949.11 -2519.83,-949.11 v1(-2519.72,-949.22) ; v1(-2555,685) -2554.92,684.92 -2512.28,684.92 U12.10@-2512.2,684.84 ; v1(-2555,785) v1@-2554.38,785 ; v1(-2555,920) -2552.58,917.58 -2517.53,917.58 -2516.08,919.03 U12.1@-2512.2,915.16 ; U12.9@-2512.2,710.43 -2527.95,710.43 -2552.52,735 v1(-2555,735) -2554.49,735.51 -2512.72,735.51 U12.8@-2512.2,736.02 ; U12.7@-2512.2,761.61 -2527.95,761.61 -2551.34,785 v1@-2554.38,785 ; U12.6@-2512.2,791.2 -2548.17,791.2 v1@-2554.38,785 ; v1(-2438.76,970) -2438.76,1007.81 C26.2@-2438.58,1008 ; C72.2@-2371.42,-1576 -2370,-1577.42 v1(-2370,-1620) ; R112.1@-2371.38,-964 -2370.38,-965 v1(-2330,-965) ; R101.1@-2371.38,-760 v1(-2325,-760) ; C54.2@-2371.42,-556 -2370.47,-556 -2351.1,-575.37 -2349.19,-575.37 -2335,-589.56 v1(-2335,-590) ; R92.1@-2371.38,-488 -2369.38,-490 v1(-2335,-490) ; R90.1@-2371.38,-420 R88.1@-2371.38,-352 R87.1@-2371.38,-284 -2370.47,-284 -2350.11,-263.64 -2343.64,-263.64 v1(-2340,-260) v1@-2338.64,-261.36 ; R83.1@-2371.38,-216 -2370.47,-216 -2334.47,-180 v1(-2330,-180) ; R81.1@-2371.38,-148 -2370.47,-148 v1@-2342.11,-176.36 ; R79.1@-2371.38,-80 -2370.47,-80 v1@-2335.47,-45 ; R75.1@-2371.38,-12 -2370.47,-12 -2337.47,-45 v1@-2335.47,-45 ; C42.2@-2371.42,124 -2356.56,138.86 -2332.27,138.86 v1(-2330.58,140.55) ; D18.1@-2358.66,434 -2320,472.66 v1(-2320,475) -2320,478.34 D17.1@-2358.66,517 -2320.66,555 v1(-2320,555) -2323.64,558.64 -2323.64,564.97 D16.1@-2358.66,600 ; v1(-2335,-45) v1@-2335.47,-45 ; U12.19@-2282.8,895 -2282.08,894.28 -2245.72,894.28 v1(-2245,895) ; v1(-1465,2226.5) -1437.36,2198.86 -1403.44,2198.86 C14.2@-1388.58,2184 ; v1(-1460,-1980) C76.2@-1388.58,-1980 ; v1(-1460,-850) -1438.08,-828.08 -1400.66,-828.08 C63.2@-1388.58,-816 ; v1(-1455.97,1913.84) -1455.88,1913.93 -1392.65,1913.93 -1391.58,1915 C18.2@-1388.58,1912 ; v1(-1454.73,-1087.88) -1452.61,-1090 -1390.58,-1090 C69.2@-1388.58,-1088 ; v1(-1447.35,1064.09) -1445.07,1066.36 -1435.89,1066.36 -1389.53,1020 C25.2@-1388.58,1020 ; v1@-1441.36,-2116.36 v1(-1442.62,-2117.62) -1445,-2120 -1392.58,-2120 C78.2@-1388.58,-2116 ; v1@-1441.36,883.64 v1(-1445,880) -1392.58,880 C28.2@-1388.58,884 ; v1(-1440.51,772.67) -1436.88,769.04 -1418.54,769.04 -1412.36,762.86 -1403.44,762.86 C31.2@-1388.58,748 ; v1(-1440,-2235) -1414.5,-2235 -1412.36,-2237.14 -1403.44,-2237.14 C80.2@-1388.58,-2252 ; v1(-1439.5,2065) -1414.5,2065 -1412.36,2062.86 -1403.44,2062.86 C16.2@-1388.58,2048 ; v1(-1438.6,-937.81) -1414.78,-937.81 -1414.41,-938.18 -1402.39,-938.18 C66.2@-1388.58,-952 ; v1(-1435,-2390) -1390.58,-2390 C86.2@-1388.58,-2388 ; v1(-1435,-680) C59.2@-1388.58,-680 ; v1(-1435,615) -1391.58,615 C37.2@-1388.58,612 ; v1(-1435,2320) C10.2@-1388.58,2320 ; v1(-1425,-240) -1425,-239.47 -1389.53,-204 C52.2@-1388.58,-204 ; v1(-1425,-35) v1@-1424.53,-35 ; C49.2@-1388.58,-68 -1389.53,-68 -1422.53,-35 v1@-1424.53,-35 ; C45.2@-1388.58,0 -1389.53,0 v1@-1424.53,-35 ; v1(-1255.5,-160) -1251.86,-156.36 -1243.86,-156.36 U14.15@-1212.5,-125 ; v1(-1255,-125) U14.15@-1212.5,-125 ; v1(-1245,160) -1239.86,160 -1231.86,168 -1193.5,168 U14.9@-1186.5,175 -1190.56,179.06 -1229.06,179.06 v1(-1245,195) ; U14.15@-1186.5,-125 U14.15@-1212.5,-125 ; v1(-1180,-1320) -1180,-1343 -1173,-1350 U22.7@-1162.75,-1350 -1152,-1350 -1145,-1343 v1(-1145,-1320) ; v1(-1180,1680) -1180,1657 -1173,1650 U7.7@-1162.75,1650 -1157,1650 -1150,1657 v1(-1150,1680) ; v1(1150,1320) 1150,1343 1157,1350 U8.7@1162.75,1350 1171,1350 1178,1343 v1(1178,1320) ; v1(1155,-1680) 1155,-1657 1162,-1650 U23.7@1162.75,-1650 1178,-1650 1185,-1657 v1(1185,-1680) ; U15.15@1186.5,125 U15.15@1212.5,125 ; v1(1245,-195) 1229.06,-179.06 1190.56,-179.06 U15.9@1186.5,-175 1193.5,-168 1231.86,-168 1239.86,-160 v1(1245,-160) ; v1(1255,125) U15.15@1212.5,125 ; v1(1255.5,160) 1251.86,156.36 1243.86,156.36 U15.15@1212.5,125 ; C83.2@1388.58,-2320 v1(1440,-2320) ; C79.2@1388.58,-2184 1389.98,-2185.4 1440.4,-2185.4 1458.99,-2203.99 v1(1458.99,-2206.01) ; C77.2@1388.58,-2048 1391.87,-2051.3 v1(1428.92,-2051.3) ; C75.2@1388.58,-1912 1391.58,-1915 1392.12,-1914.46 v1(1455.51,-1914.46) ; C68.2@1388.58,-1020 1389.53,-1020 1430.89,-1061.36 1450.86,-1061.36 v1(1454.5,-1065) ; C65.2@1388.58,-884 1392.58,-880 v1(1444.5,-880) 1445,-880 v1@1441.36,-883.64 ; C62.2@1388.58,-748 1403.44,-762.86 1412.36,-762.86 1414.5,-765 v1(1440,-765) ; C55.2@1388.58,-612 1390.58,-610 v1(1435,-610) ; C48.2@1388.58,0 1389.53,0 v1@1424.53,35 ; C43.2@1388.58,68 1389.53,68 1422.53,35 v1@1424.53,35 ; C39.2@1388.58,204 1389.53,204 1425,239.47 v1(1425,240) ; C34.2@1388.58,680 1393.58,675 v1(1440,675) ; C30.2@1388.58,816 1402.57,830 v1(1460,830) ; C27.2@1388.58,952 1403.44,937.14 1412.36,937.14 1414.5,935 v1(1440,935) ; C23.2@1388.58,1088 1390.83,1090.25 1439.61,1090.25 1449.42,1080.44 v1(1454.49,1080.44) ; C17.2@1388.58,1980 1389.53,1980 1434.5,1935.03 v1(1460,1935) ; C15.2@1388.58,2116 1392.58,2120 v1(1443.59,2120) 1445,2120 v1@1441.36,2116.36 ; C13.2@1388.58,2252 1403.44,2237.14 1412.36,2237.14 1414.5,2235 1438.94,2235 v1(1440,2236.06) ; C7.2@1388.58,2388 1390.58,2390 v1(1435.53,2390) ; v1(1425,35) v1@1424.53,35
  Bottom Layer w8: J13.MH1@-6241.34,2952.09 -6239.25,2950 v1(-6185,2950) ; J13.MH2@-6241.34,3287.91 -6239.25,3290 v1(-6185,3290) ; C203.2@-4278.58,-624 -4279.53,-624 -4315,-588.53 v1(-4315,-586) -4311.36,-582.36 -4305.89,-582.36 -4279.53,-556 R290.1@-4278.62,-556 ; C188.2@-4278.58,-284 -4279.53,-284 -4315,-248.53 v1(-4315,-246) -4311.36,-242.36 -4305.89,-242.36 -4279.53,-216 R273.1@-4278.62,-216 ; C173.2@-4278.58,56 -4279.53,56 -4315,91.47 v1(-4315,94) -4311.36,97.64 -4305.89,97.64 -4279.53,124 R259.1@-4278.62,124 ; C161.2@-4278.58,396 -4279.53,396 -4315,431.47 v1(-4315,434) -4311.36,437.64 -4305.89,437.64 -4279.53,464 R243.1@-4278.62,464 ; v1(-4165,-786) -4161.36,-782.36 -4151.89,-782.36 -4129.53,-760 C211.2@-4128.58,-760 ; v1(-4165,-446) -4161.36,-442.36 -4151.89,-442.36 -4129.53,-420 C193.2@-4128.58,-420 ; v1(-4165,-106) -4161.36,-102.36 -4151.89,-102.36 -4129.53,-80 C181.2@-4128.58,-80 ; v1(-4165,234) -4161.36,237.64 -4151.89,237.64 -4129.53,260 C168.2@-4128.58,260 ; C215.2@-4071.42,-828 -4069.42,-826 v1(-4030,-826) ; C200.2@-4071.42,-556 v1(-4030,-556) ; C196.2@-4071.42,-488 -4069.42,-486 v1(-4030,-486) ; C186.2@-4071.42,-216 v1(-4030,-216) ; C184.2@-4071.42,-148 -4069.42,-146 v1(-4030,-146) ; C171.2@-4071.42,124 v1(-4030,124) ; C169.2@-4071.42,192 -4069.42,194 v1(-4030,194) ; C156.2@-4071.42,464 v1(-4030,464) ; v1(-4005,-736) -4001.36,-732.36 -3993.71,-732.36 -3978.94,-717.59 U41.3@-3961.22,-717.59 -3928.46,-717.59 v1@-3916.77,-729.28 ; v1(-4005,-396) -4001.36,-392.36 -3993.71,-392.36 -3978.94,-377.59 U40.3@-3961.22,-377.59 -3928.46,-377.59 v1@-3916.77,-389.28 ; v1(-4005,-56) -4001.36,-52.36 -3993.71,-52.36 -3978.94,-37.59 U37.3@-3961.22,-37.59 -3928.46,-37.59 v1@-3916.77,-49.28 ; v1(-4005,284) -4001.36,287.64 -3993.71,287.64 -3978.94,302.41 U32.3@-3961.22,302.41 -3928.46,302.41 v1@-3916.77,290.72 ; v1@-3993.78,-742.08 U41.2@-3962.33,-742.08 ; v1@-3993.78,-402.08 U40.2@-3962.33,-402.08 ; v1@-3993.78,-62.08 U37.2@-3962.33,-62.08 ; v1@-3993.78,277.92 U32.2@-3962.33,277.92 ; U41.2@-3961.22,-743.18 U41.2@-3962.33,-742.08 ; U40.2@-3961.22,-403.18 U40.2@-3962.33,-402.08 ; U37.2@-3961.22,-63.18 U37.2@-3962.33,-62.08 ; U32.2@-3961.22,276.82 U32.2@-3962.33,277.92 ; v1@-3916.16,-728.67 v1@-3916.77,-729.28 ; v1@-3916.16,-388.67 v1@-3916.77,-389.28 ; v1@-3916.16,-48.67 v1@-3916.77,-49.28 ; v1@-3916.16,291.33 v1@-3916.77,290.72 ; v1(-3915,-731) -3915.05,-731 v1@-3916.77,-729.28 ; v1(-3915,-391) -3915.05,-391 v1@-3916.77,-389.28 ; v1(-3915,-51) -3915.05,-51 v1@-3916.77,-49.28 ; v1(-3915,289) -3915.05,289 v1@-3916.77,290.72 ; v1(-3780,-691) -3779.5,-691.5 -3739.28,-691.5 U41.11@-3738.78,-692 -3738.28,-691.5 -3695.5,-691.5 v1(-3695,-691) ; v1(-3780,-351) -3779.5,-351.5 -3739.28,-351.5 U40.11@-3738.78,-352 -3738.28,-351.5 -3695.5,-351.5 v1(-3695,-351) ; v1(-3780,-11) -3779.5,-11.5 -3739.28,-11.5 U37.11@-3738.78,-12 -3738.28,-11.5 -3695.5,-11.5 v1(-3695,-11) ; v1(-3780,329) -3779.5,328.5 -3739.28,328.5 U32.11@-3738.78,328 -3738.28,328.5 -3695.5,328.5 v1(-3695,329) ; v1(-3270,-1235) -3229.62,-1235 R331.1@-3228.62,-1236 ; v1(-3270,-1160) R326.1@-3228.62,-1160 ; v1(-3270,-115) -3266.36,-118.64 -3258.89,-118.64 C183.2@-3229.53,-148 ; v1(-3270,400) -3231.58,400 C160.2@-3228.58,403 ; v1(-3270,460) -3232.58,460 C155.2@-3228.58,464 ; v1(-3270,740) -3269.8,740.2 -3232.83,740.2 R227.1@-3228.62,736 ; v1(-3270,805) -3229.58,805 C142.2@-3228.58,804 ; v1(-3270,870) -3230.62,870 R222.1@-3228.62,872 ; v1(-3267.7,356.32) -3265.16,358.86 -3203.24,358.86 -3172.37,328 C164.2@-3171.42,328 ; v1(-3265,-1475) v1@-3264.53,-1475 ; v1(-3265,-865) -3265,-863.47 -3229.53,-828 C214.2@-3228.58,-828 ; v1(-3265,260) C166.2@-3228.58,260 ; v1(-3265,535) -3232.53,535 -3229.53,532 R241.1@-3228.62,532 ; v1@-3260.89,-111.36 -3229.53,-80 C179.2@-3228.58,-80 ; C190.2@-3232.55,-352 -3235.43,-352 -3266.36,-321.07 -3266.36,-313.64 v1(-3270,-310) -3266.36,-306.36 -3251.89,-306.36 -3229.53,-284 -3268.53,-245 v1(-3270,-245) -3266.36,-241.36 -3254.89,-241.36 C185.2@-3229.53,-216 ; R344.1@-3228.62,-1508 -3229.53,-1508 -3262.53,-1475 v1@-3264.53,-1475 ; R341.1@-3228.62,-1440 -3229.53,-1440 v1@-3264.53,-1475 ; C202.2@-3228.58,-624 -3229.53,-624 -3259.89,-593.64 -3266.36,-593.64 v1(-3270,-590) -3266.36,-586.36 -3259.89,-586.36 -3229.53,-556 C199.2@-3228.58,-556 ; C185.2@-3228.58,-216 C185.2@-3229.53,-216 ; C183.2@-3228.58,-148 C183.2@-3229.53,-148 ; v1(-3119.58,-17.35) -3119.58,-14.43 -3107.5,-2.36 -3107.5,10.23 -3104.5,13.23 U36.7@-3092,13.23 ; D42.1@-3029.13,-3700 -3029.13,-3698.03 -2991,-3659.9 -2991,-3652.88 v1(-2987.37,-3649.25) ; D32.1@-3029.13,3700 -3029.13,3698.03 -2994.74,3663.64 -2988.64,3663.64 v1(-2985,3660) ; v1(-2870,-1640.5) -2833.12,-1640.5 -2832.62,-1640 R351.1@-2828.62,-1644 ; v1(-2870,-1095) -2833.58,-1095 C229.2@-2828.58,-1100 ; v1(-2869.52,-47.96) -2865.48,-47.96 -2829.53,-12 C176.2@-2828.58,-12 ; v1(-2868.98,543.89) -2840.47,543.89 C151.2@-2828.58,532 ; v1(-2865,430) v1@-2863.53,430 ; v1(-2864.08,-860.83) -2864.08,-861.45 -2829.53,-896 R313.1@-2828.62,-896 ; v1@-2857.94,-51.59 -2829.53,-80 -2844.39,-94.86 -2874.86,-94.86 v1(-2875,-95) -2875,-100.14 -2867.36,-107.78 -2867.36,-109.26 -2843.48,-133.14 -2843.48,-134.04 -2829.53,-148 R269.1@-2828.62,-148 ; R347.1@-2828.62,-1576 -2829.53,-1576 -2866.36,-1539.16 -2866.36,-1523.64 v1(-2870,-1520) -2840.58,-1520 C241.2@-2828.58,-1508 ; C238.2@-2828.58,-1440 -2838.58,-1430 v1(-2900,-1430) -2896.36,-1426.36 -2883.89,-1426.36 -2829.53,-1372 C235.2@-2828.58,-1372 ; R330.1@-2828.62,-1236 -2829.62,-1235 v1(-2875,-1235) -2871.36,-1231.36 -2871.36,-1209.84 -2829.53,-1168 C230.2@-2828.58,-1168 ; C228.2@-2828.58,-1032 -2829.53,-1032 -2870,-991.53 v1(-2870,-990) -2854.94,-974.94 -2839.52,-974.94 C224.2@-2828.58,-964 ; C163.2@-2828.58,328 -2828.58,395.05 v1@-2863.53,430 ; C154.2@-2828.58,464 -2829.53,464 v1@-2863.53,430 ; C209.2@-2771.42,-760 -2770.47,-760 -2743.97,-733.5 -2738.44,-733.5 v1(-2734.8,-729.86) ; C201.2@-2771.42,-624 -2770.47,-624 -2736.79,-590.31 v1(-2734.69,-590.31) ; C189.2@-2771.42,-352 -2756.56,-337.14 -2737.14,-337.14 v1(-2735,-335) ; C191.2@-2770.47,-420 -2755.61,-405.14 -2741.89,-405.14 -2736.3,-399.55 v1(-2731.16,-399.55) ; v1(-2655,830) v1@-2655,832.3 ; v1(-2069.09,318.32) -2038.25,318.32 C162.2@-2028.58,328 ; C165.2@-1971.42,260 -1956.56,245.14 -1935.45,245.14 v1(-1934.4,244.09) ; U35.7@-1883.75,13.23 -1882.86,14.11 -1835.89,14.11 v1(-1835,15) ; U35.5@-1883.75,64.41 -1848.46,64.41 v1@-1837.87,75 ; U35.4@-1883.75,90 -1880.75,87 -1852.14,87 -1840.14,75 v1@-1837.87,75 ; v1(-1835,75) v1@-1837.87,75 ; v1(-1465,2185) -1421.25,2185 C99.2@-1420.25,2184 -1420.25,2194.88 -1448.23,2222.86 -1461.36,2222.86 v1(-1465,2226.5) ; v1(-1465,2285) -1436.25,2285 C97.2@-1435,2283.75 ; v1@-1464.75,-2024.75 -1461.36,-2021.36 -1450.73,-2021.36 -1420.25,-1990.88 C248.2@-1420.25,-1980 v1(-1460,-1980) ; v1(-1464.5,-2025) -1460.86,-2028.64 -1445.73,-2028.64 -1420.25,-2054.12 C254.2@-1420.25,-2065 -1438.01,-2082.76 -1438.01,-2107.87 -1442.62,-2112.48 v1(-1442.62,-2117.62) ; v1(-1460,-850) -1454.86,-850 -1449.5,-844.64 -1438.01,-844.64 -1425.89,-832.52 C213.2@-1425.89,-823.64 ; v1(-1460,-815) -1421.25,-815 C213.2@-1420.25,-816 ; v1(-1460,-720) -1431.25,-720 C208.2@-1420.25,-731 ; v1(-1447.35,1064.09) -1443.72,1060.45 -1443.72,1054.35 -1420.25,1030.88 C129.2@-1420.25,1020 -1420.25,1009.12 -1450.73,978.64 -1461.36,978.64 v1(-1465,975) -1461.36,971.36 -1445.73,971.36 -1420.25,945.88 C135.2@-1420.25,935 -1438.01,917.24 -1438.01,892.13 -1445,885.14 v1(-1445,880) -1441.36,876.36 -1425.89,876.36 -1399.53,850 C140.2@-1398.58,850 ; v1@-1445,-2120 -1441.36,-2123.64 -1425.89,-2123.64 -1399.53,-2150 C258.2@-1398.58,-2150 ; v1(-1440.51,772.67) v1@-1436.88,769.04 ; v1(-1440,-2490) C268.2@-1398.58,-2490 ; v1(-1440,-2235) v1@-1437.86,-2232.86 ; v1(-1440,-510) C198.2@-1398.58,-510 ; v1(-1440,515) -1403.58,515 C153.2@-1398.58,510 ; v1@-1440,2065 -1436.36,2068.64 -1429.89,2068.64 -1399.53,2099 C106.2@-1398.58,2099 ; v1(-1439.5,2065) -1435.86,2061.36 v1@-1429.89,2061.36 ; v1(-1438.6,-937.81) v1@-1435.19,-937.81 ; C99.2@-1438.01,2192.13 C99.2@-1438.01,2199.33 ; v1(-1435,-2390) v1@-1435,-2389.47 ; v1(-1435,-680) -1435,-703.75 C208.2@-1430,-708.75 ; v1(-1435,615) v1@-1430.53,615 ; v1@-1433.53,2320 v1(-1435,2320) C97.2@-1435,2283.75 ; v1(-1429.78,2465.22) -1426.14,2468.86 -1420.67,2468.86 -1399.53,2490 C92.2@-1398.58,2490 ; v1@-1428.51,-932.86 -1414.39,-918.74 -1414.39,-915.86 -1407.96,-909.43 C220.2@-1405.08,-909.43 ; C97.2@-1420.25,2269 C97.2@-1435,2283.75 ; C270.2@-1398.58,-2558 -1396.23,-2560.35 v1(-1396.23,-2598.77) ; v1(-1370,-1745) -1366.36,-1741.36 -1366.36,-1727.99 -1342.37,-1704 C247.2@-1341.42,-1704 ; v1(-1360,-2650) -1338.8,-2671.2 -1331.55,-2671.2 -1321.52,-2681.23 U47.2@-1321.52,-2683.77 ; v1(-1360,355) -1360,353.21 -1339.4,332.61 -1335.36,332.61 -1322.76,320 U34.2@-1311.93,320 ; C90.2@-1341.63,2548.02 -1313.64,2576.01 v1@-1313.64,2591.36 ; C195.2@-1341.42,-442 -1340.65,-441.23 v1(-1340.65,-405.44) ; C158.2@-1341.42,442 -1340,440.58 v1(-1340,405) ; C128.2@-1341.42,1296 -1340.42,1295 v1(-1300,1295) ; C90.2@-1341.42,2558 -1350,2566.58 v1(-1350,2600) -1346.36,2603.64 -1346.36,2618.99 -1318.37,2646.98 -1316.31,2646.98 -1320.7,2651.36 -1351.36,2651.36 v1(-1355,2655) -1351.36,2658.64 -1344.12,2658.64 -1322.76,2680 U27.2@-1311.93,2680 ; U34.2@-1322.76,318.21 -1335.36,305.6 -1339.4,305.6 v1(-1360,285) -1358.8,283.8 -1313.13,283.8 U34.3@-1311.93,282.6 ; U47.3@-1311.93,-2717.4 -1316.93,-2712.4 -1352.6,-2712.4 v1(-1356.23,-2708.77) -1355.56,-2708.77 -1339.4,-2692.61 -1335.36,-2692.61 -1322.76,-2680 U47.2@-1311.93,-2680 ; U39.3@-1311.93,-357.4 -1313.13,-356.2 -1353.8,-356.2 v1(-1355,-355) -1355,-352.24 -1322.76,-320 U39.2@-1311.93,-320 ; U27.3@-1311.93,2642.6 U27.3@-1310,2640.67 ; v1(-1310,2595) U27.3@-1310,2640.67 ; U27.2@-1310,2678.07 U27.3@-1310,2640.67 ; v1(-1275,2020.5) -1269.86,2020.5 -1255.86,2034.5 -1247.97,2034.5 -1247.62,2034.84 U29.5@-1195.87,2034.84 ; v1(-1265,-2273) -1259.86,-2273 -1252.02,-2265.16 U45.5@-1195.87,-2265.16 ; v1(-1259.86,-975) -1250.02,-965.16 U43.5@-1195.87,-965.16 ; v1(-1259.86,725.16) -1259.7,725.16 -1250.02,734.84 U31.5@-1195.87,734.84 ; v1(-620,3655) -616.36,3658.64 -610.26,3658.64 -570.87,3698.03 D31.1@-570.87,3700 ; v1(-615,-3650) -615,-3653.9 -570.87,-3698.03 D41.1@-570.87,-3700 ; U44.5@1195.87,-2034.84 1245.02,-2034.84 1259.33,-2020.53 v1(1264.47,-2020.53) ; U42.5@1195.87,-734.84 1250.02,-734.84 1259.7,-725.16 v1(1259.86,-725.16) ; U30.5@1195.87,965.16 1250.02,965.16 v1(1259.86,975) ; U28.5@1195.87,2265.16 1251.08,2265.16 1257.82,2271.9 v1(1262.96,2271.9) ; v1(1304.53,2495) 1335.47,2495 C91.2@1340.47,2490 ; v1(1305.2,1699.8) 1337.22,1699.8 C115.2@1341.42,1704 ; v1(1305.5,-1295) 1340.42,-1295 C231.2@1341.42,-1296 ; v1(1308.95,386.82) 1308.95,365.38 U33.3@1316.93,357.4 U33.2@1316.93,320 v1(1355.31,320) ; U46.2@1311.93,-2680 1320.72,-2671.2 1336.19,-2671.2 v1@1348.63,-2658.77 ; U46.3@1311.93,-2642.6 1320.72,-2651.39 1341.25,-2651.39 v1@1348.63,-2658.77 ; U38.2@1311.93,-320 1318.29,-313.64 v1@1351.36,-313.64 ; U26.3@1311.93,2717.4 1320.72,2708.61 1341,2708.61 v1@1349.6,2700 ; v1(1335,-2600) 1335,-2564.42 C269.2@1341.42,-2558 1342.37,-2558 1382.76,-2517.61 1382.76,-2504.86 1397.63,-2490 C267.2@1398.58,-2490 ; C194.2@1341.42,-442 1345,-438.42 v1(1345,-405) ; C157.2@1341.42,442 1342.37,442 1357.24,427.14 1357.24,421.08 1373.86,404.46 v1(1373.86,402.2) ; C89.2@1341.42,2558 1339.53,2559.9 1339.53,2602.39 1356.36,2619.23 1356.36,2636.36 v1(1360,2640) 1356.36,2643.64 1356.36,2650.43 1339.4,2667.39 1335.36,2667.39 1322.76,2680 U26.2@1311.93,2680 1320.72,2688.8 1338.18,2688.8 1349.39,2700 v1@1349.6,2700 ; v1(1353.77,-2658.77) v1@1348.63,-2658.77 ; v1(1354.53,2700) v1@1349.6,2700 ; v1(1355,-310) 1350.16,-310 1322.76,-282.6 U38.3@1311.93,-282.6 1320.72,-273.8 1346.06,-273.8 1349.86,-270 v1(1355,-270) ; C255.2@1398.58,-2099 1399.53,-2099 1414.39,-2084.14 1414.39,-2083.19 1428.86,-2068.71 v1@1428.86,-2056.14 ; C217.2@1398.58,-850 1399.53,-850 1425.89,-876.36 1440.86,-876.36 v1(1444.5,-880) ; C197.2@1398.58,-510 1399.53,-510 1437.86,-548.33 v1(1437.86,-550.93) ; C152.2@1398.58,510 1403.44,505.14 v1(1440,505.14) ; C137.2@1398.58,901 1402.71,905.14 v1(1440,905.14) ; C137.2@1398.58,918 1413.44,932.86 1437.86,932.86 v1(1440,935) v1@1436.36,938.64 ; C101.2@1398.58,2150 1399.53,2150 1425.89,2123.64 1439.96,2123.64 v1(1443.59,2120) ; C259.2@1420.25,-2184 1420.25,-2187.24 1438.01,-2205 1438.01,-2206.01 v1(1458.99,-2206.01) ; C146.2@1420.25,731 C146.2@1426.25,725 ; C141.2@1420.25,816 1420.25,812.9 1438.01,795.14 v1(1460,795.14) ; v1@1423.78,-2051.3 v1(1428.92,-2051.3) ; C141.2@1425.89,823.64 v1@1453.64,823.64 ; v1@1435,-610.53 v1(1435,-610) ; v1@1436.81,2232.86 v1(1440,2236.06) ; v1@1437.86,-767.14 v1(1440,-765) ; C141.2@1438.01,807.87 1438.01,823.56 1453.71,823.56 1460,829.86 v1(1460,830) ; v1(1440,-2320) 1438.01,-2318.01 1438.01,-2256.61 1429.89,-2248.48 1435.69,-2242.68 1438.01,-2240.36 1438.01,-2245 v1(1460,-2245) ; v1(1440,675) 1438.01,676.99 1438.01,713.24 C146.2@1426.25,725 ; v1@1445,-880 1445,-885.14 1438.01,-892.13 1438.01,-917.24 C222.2@1420.25,-935 1420.25,-945.88 1445.73,-971.36 1461.36,-971.36 v1(1465,-975) 1461.36,-978.64 1450.73,-978.64 1420.25,-1009.12 C227.2@1420.25,-1020 1420.25,-1030.88 1454.37,-1065 v1(1454.5,-1065) ; v1@1445,2120 1445,2114.86 1438.01,2107.87 1438.01,2082.76 C108.2@1420.25,2065 1420.25,2054.12 1445.73,2028.64 1457.86,2028.64 v1(1461.5,2025) ; v1(1460,1935) 1456.36,1938.64 1450.73,1938.64 1420.25,1969.12 C112.2@1420.25,1980 1420.25,1990.88 1450.73,2021.36 1461.36,2021.36 v1@1465,2025 ; v1(1465,725) C146.2@1426.25,725 ; U41.2@-3962.33,-742.08 -3929.57,-742.08 v1@-3916.77,-729.28 ; U40.2@-3962.33,-402.08 -3929.57,-402.08 v1@-3916.77,-389.28 ; U37.2@-3962.33,-62.08 -3929.57,-62.08 v1@-3916.77,-49.28 ; U32.2@-3962.33,277.92 -3929.57,277.92 v1@-3916.77,290.72 ; C185.2@-3229.53,-216 -3256.89,-188.64 -3266.36,-188.64 v1(-3270,-185) -3266.53,-185 C183.2@-3229.53,-148
  other v1: -5400,-3800 -5200,-3800 -5000,-3800 -4800,-3800 -4600,-3800 -4400,-3800 -4200,-3800 -4000,-3800 -3800,-3800 -3600,-3800 -3400,-3800 -3200,-3800 -3000,-3800 -2800,-3800 -2600,-3800 -2400,-3800 -2200,-3800 -2000,-3800 -1800,-3800 -1600,-3800 -600,-3800 -400,-3800 -200,-3800 0,-3800 200,-3800 400,-3800 600,-3800 -1500,-3700 -5400,-3600 600,-3600 -1500,-3500 -5400,-3400 -600,-3400 600,-3400 -1500,-3300 -1300,-3300 -1100,-3300 -900,-3300 -700,-3300 800,-3300 1000,-3300 1200,-3300 1400,-3300 1600,-3300 -5400,-3200 1600,-3100 -5400,-3000 1600,-2900 -5400,-2800 1600,-2700 -5400,-2600 1600,-2500 1185,-2410 1220,-2410 1255,-2410 -5400,-2400 -1210,-2395 -1180,-2395 1255,-2375 1255,-2340 1255,-2305 1251.54,-2239.87 -5400,-2200 -1251.54,-2060.13 -5400,-2000 -1255,-1995 -1255,-1960 -1255,-1925 1180,-1905 1210,-1905 -1255,-1890 -1220,-1890 -1185,-1890 -5400,-1800 1620.5,-1705 1620.5,-1635 -1558.5,-1605 -5400,-1600 1620.5,-1565 -1558.5,-1535 1620.5,-1500 -1558.5,-1465 1620.5,-1430 -5400,-1400 -1558.5,-1395 1620.5,-1365 -1558.5,-1330 -5400,-1200 1185,-1110 1220,-1110 1255,-1110 -1210,-1095 -1180,-1095 1255,-1075 1255,-1040 1255,-1005 -5400,-1000 1251.54,-939.87 -5400,-800 -1251.54,-760.13 -1255,-695 -1255,-660 -1255,-625 1180,-605 1210,-605 -5400,-600 -1255,-590 -1220,-590 -1185,-590 -5400,-400 1200,-400 -5400,-200 1600,-200 -5400,0 1600,0 -5400,200 1600,200 -5400,400 1200,400 1600,400 1185,590 1220,590 1255,590 -5400,600 1600,600 -1210,605 -1180,605 1255,625 1255,660 1255,695 1251.54,760.13 -5400,800 1600,800 -2570,815 -1251.54,939.87 -5400,1000 -1255,1005 -1255,1040 -1255,1075 1180,1095 1210,1095 -1255,1110 -1220,1110 -1185,1110 -5400,1200 1621.5,1295 1621.5,1365 -1560,1395 -5400,1400 1621.5,1435 -1560,1465 1621.5,1500 -1560,1535 1621.5,1570 -5400,1600 -1560,1605 1621.5,1635 -1560,1670 -5400,1800 1185,1890 1220,1890 1255,1890 -5700,1900 -5500,1900 -1210,1905 -1180,1905 1255,1925 1255,1960 1255,1995 1251.54,2060.13 -5700,2100 -1251.54,2239.87 -5700,2300 -1255,2305 -1255,2340 -1255,2375 1180,2395 1210,2395 -6100,2400 -5900,2400 -1255,2410 -1220,2410 -1185,2410 -6100,2600 1339.53,2600 1200,2700 -6100,2800 1600,2900 -6145,3070 -6115,3070 -6035,3070 -6005,3070 -6145,3100 -6115,3100 -6035,3100 -6005,3100 1600,3100 -6000,3300 -5800,3300 -1500,3300 -1300,3300 -1100,3300 -900,3300 -700,3300 800,3300 1000,3300 1200,3300 1400,3300 1600,3300 -600,3400 600,3400 -1500,3500 600,3600 -1530,3635 -1530,3670 -1530,3705 -1530,3740 -1530,3775 -5600,3800 -5400,3800 -5200,3800 -5000,3800 -4800,3800 -4600,3800 -3200,3800 -3000,3800 -2600,3800 -2400,3800 -2200,3800 -2000,3800 -1800,3800 -600,3800 -400,3800 -200,3800 0,3800 200,3800 400,3800 600,3800 -1530,3810 -1530,3845
GND_P: C46.2 C50.1 C53.2 C175.2 C177.2 C182.2 R71.2 U14.2 U14.7 U14.8 | length 729.8
  Top Layer w8: v1(-830,205) -830,182 U14.8@-823,175 ; U14.2@-813.5,-125 v1(-760,-125) ; v1(-800,205) -800,182 -807,175 U14.8@-813.5,175 ; U14.7@-797,132 U14.8@-797,168 ; C46.2@-668.58,0 R71.2@-668.62,68 R71.2@-668.62,68 -682.58,81.96 -741.96,81.96 -778,118 -806.5,118 U14.7@-813.5,125 -823,125 -830,132 -830,168 U14.8@-823,175 ; C53.2@-611.42,-204 -610.47,-204 v1@-576.47,-170 ; C50.1@-611.42,-136 -610.47,-136 v1@-576.47,-170 ; v1(-575,-170) v1@-576.47,-170 ; U14.8@-823,175 U14.8@-813.5,175 ; U14.8@-823,175 U14.8@-813.5,175
  Bottom Layer w8: C182.2@-611.42,-136 -610.47,-136 -576.47,-170 v1(-575,-170) ; C177.2@-611.42,-68 -610.47,-68 -575.5,-33.03 v1(-571.24,-33.03) ; C175.2@-611.42,0 -610.47,0 v1@-581.08,-29.39
GND_S: C38.2 C41.1 C47.2 C170.2 C172.2 C174.2 R77.2 U15.2 U15.7 U15.8 | length 730.4
  Top Layer w8: v1(575,170) v1@576.47,170 ; C41.1@611.42,136 610.47,136 v1@576.47,170 ; C38.2@611.42,204 610.47,204 v1@576.47,170 ; C47.2@668.58,0 C47.2@668.58,0 R77.2@668.62,-68 682.58,-81.96 744.46,-81.96 787.5,-125 U15.7@792,-125 ; v1(760,125) U15.2@813.5,125 ; U15.7@789.75,-127.25 U15.7@792,-125 ; v1(805,-205) 805,-182 812,-175 U15.8@813.5,-175 ; U15.8@830,-168 U15.7@830,-132 ; v1(835,-205) 835,-182 828,-175 U15.8@813.5,-175 ; U15.7@792,-125 U15.7@813.5,-125 807,-125 800,-132 800,-168 807,-175 U15.8@813.5,-175
  Bottom Layer w8: v1(575,35) v1@575.47,35 ; v1(575,170) 576.47,170 610.47,136 C170.2@611.42,136 ; C174.2@611.42,0 610.47,0 v1@575.47,35 ; C172.2@611.42,68 610.47,68 577.47,35 v1@575.47,35
GPIO08: R127.2 U9.57 | length 1837.7
  Top Layer w8: v1(-3071.5,-70) -3140,-70 -3172,-102 -3172,-1038 -2880,-1330 -2854.62,-1330 -2843.48,-1318.86 -2843.48,-1317.96 -2829.53,-1304 R127.2@-2828.62,-1304 ; v1(-2985,-15) -2985,10 U9.57@-2980,15
  Bottom Layer w8: v1(-3071.5,-70) -2958.94,-70 -2919.5,-30.56 -2919.5,4.5 -2925.98,10.98 -2959.02,10.98 -2980,-10 v1@-2985,-10
GPIO09: R131.2 U9.59 | length 1839.2
  Top Layer w8: v1(-3095.47,-44.5) -3139.5,-44.5 -3188,-93 -3188,-1049.37 -2887.37,-1350 -2850.62,-1350 -2843.48,-1357.14 -2843.48,-1358.04 -2829.53,-1372 R131.2@-2828.62,-1372 ; U9.59@-2965,45 -2961.4,41.4 -2929.94,41.4 -2919.1,30.56 -2919.1,0.94 -2940.04,-20 v1(-2945,-20)
  Bottom Layer w8: v1(-3095.47,-44.5) -2969.5,-44.5 v1(-2945,-20)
